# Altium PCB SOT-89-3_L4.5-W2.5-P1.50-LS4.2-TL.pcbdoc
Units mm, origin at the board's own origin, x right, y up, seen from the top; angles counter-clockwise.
Board outline 18.08 x 17.35 mm, 2 copper layers (Top Layer, Bottom Layer), stack 0.07 mm thick; 1 components, 0 nets, 3 pads, 0 vias.
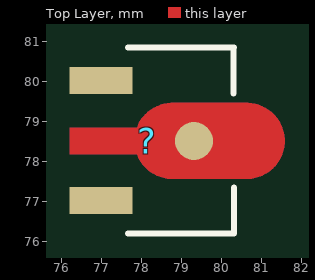
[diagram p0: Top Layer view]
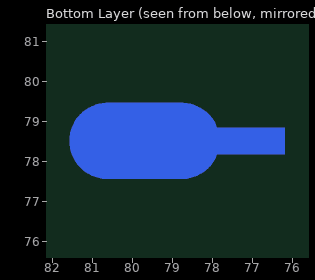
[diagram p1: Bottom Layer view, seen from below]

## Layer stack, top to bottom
Top Solder Mask Layer: solder mask 0.01, Dk 3.3
Top Layer: signal copper 0.035
Bottom Layer: signal copper 0.035
Bottom Solder Mask Layer: solder mask 0.01, Dk 3.3

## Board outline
87.927,69.85 69.85,69.85 69.85,87.202 87.927,87.202

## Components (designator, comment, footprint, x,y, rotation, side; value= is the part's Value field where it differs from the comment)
? "SOT-89-3_L4.5-W2.5-P1.50-LS4.2-TL" SOT-89-3_L4.5-W2.5-P1.50-LS4.2-TL 78.344,78.526 r0 top

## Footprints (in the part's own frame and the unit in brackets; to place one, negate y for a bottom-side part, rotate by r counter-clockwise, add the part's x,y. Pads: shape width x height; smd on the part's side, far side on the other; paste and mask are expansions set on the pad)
SOT-89-3_L4.5-W2.5-P1.50-LS4.2-TL [mm]
  rect 1.575x0.672 smd paste+0 mask+0.051: 1(-1.356,1.5) 3(-1.356,-1.5)
  round 0.95 smd: 2(0.966,-0.009)
  Top Layer region: 2.283,-0.959 0.429,-0.959 0.384,-0.958 0.34,-0.954 0.296,-0.949 0.252,-0.942 0.208,-0.933 0.165,-0.921 0.123,-0.908 0.081,-0.893 0.04,-0.875 0,-0.856 -0.04,-0.835 -0.078,-0.812 -0.115,-0.787 -0.151,-0.761 -0.185,-0.733 -0.219,-0.704 -0.251,-0.672 -0.281,-0.64 -0.31,-0.606 -0.337,-0.571 -0.362,-0.534 -0.386,-0.496 -0.408,-0.458 -0.428,-0.418 -0.447,-0.339 -2.144,-0.339 -2.144,0.321 -0.447,0.321 -0.428,0.401 -0.408,0.44 -0.386,0.479 -0.362,0.517 -0.337,0.553 -0.31,0.589 -0.281,0.623 -0.251,0.655 -0.219,0.686 -0.185,0.716 -0.151,0.744 -0.115,0.77 -0.078,0.795 -0.04,0.818 0,0.839 0.04,0.858 0.081,0.875 0.123,0.891 0.165,0.904 0.208,0.915 0.252,0.925 0.296,0.932 0.34,0.937 0.384,0.94 0.429,0.941 2.283,0.941 2.328,0.94 2.372,0.937 2.416,0.932 2.46,0.925 2.504,0.915 2.547,0.904 2.589,0.891 2.631,0.875 2.672,0.858 2.712,0.839 2.752,0.818 2.79,0.795 2.827,0.77 2.863,0.744 2.898,0.716 2.931,0.686 2.963,0.655 2.993,0.623 3.022,0.589 3.049,0.553 3.075,0.517 3.098,0.479 3.12,0.44 3.14,0.401 3.159,0.36 3.175,0.319 3.189,0.277 3.202,0.234 3.212,0.19 3.22,0.147 3.227,0.103 3.231,0.058 3.233,0.014 3.233,-0.031 3.231,-0.075 3.227,-0.12 3.22,-0.164 3.212,-0.208 3.202,-0.251 3.189,-0.294 3.175,-0.336 3.159,-0.377 3.14,-0.418 3.12,-0.458 3.098,-0.496 3.075,-0.534 3.049,-0.571 3.022,-0.606 2.993,-0.64 2.963,-0.672 2.931,-0.704 2.898,-0.733 2.863,-0.761 2.827,-0.787 2.79,-0.812 2.752,-0.835 2.712,-0.856 2.672,-0.875 2.631,-0.893 2.589,-0.908 2.547,-0.921 2.504,-0.933 2.46,-0.942 2.416,-0.949 2.372,-0.954 2.328,-0.958
  Bottom Layer region: 2.283,-0.959 0.429,-0.959 0.384,-0.958 0.34,-0.954 0.296,-0.949 0.252,-0.942 0.208,-0.933 0.165,-0.921 0.123,-0.908 0.081,-0.893 0.04,-0.875 0,-0.856 -0.04,-0.835 -0.078,-0.812 -0.115,-0.787 -0.151,-0.761 -0.185,-0.733 -0.219,-0.704 -0.251,-0.672 -0.281,-0.64 -0.31,-0.606 -0.337,-0.571 -0.362,-0.534 -0.386,-0.496 -0.408,-0.458 -0.428,-0.418 -0.447,-0.339 -2.144,-0.339 -2.144,0.321 -0.447,0.321 -0.428,0.401 -0.408,0.44 -0.386,0.479 -0.362,0.517 -0.337,0.553 -0.31,0.589 -0.281,0.623 -0.251,0.655 -0.219,0.686 -0.185,0.716 -0.151,0.744 -0.115,0.77 -0.078,0.795 -0.04,0.818 0,0.839 0.04,0.858 0.081,0.875 0.123,0.891 0.165,0.904 0.208,0.915 0.252,0.925 0.296,0.932 0.34,0.937 0.384,0.94 0.429,0.941 2.283,0.941 2.328,0.94 2.372,0.937 2.416,0.932 2.46,0.925 2.504,0.915 2.547,0.904 2.589,0.891 2.631,0.875 2.672,0.858 2.712,0.839 2.752,0.818 2.79,0.795 2.827,0.77 2.863,0.744 2.898,0.716 2.931,0.686 2.963,0.655 2.993,0.623 3.022,0.589 3.049,0.553 3.075,0.517 3.098,0.479 3.12,0.44 3.14,0.401 3.159,0.36 3.175,0.319 3.189,0.277 3.202,0.234 3.212,0.19 3.22,0.147 3.227,0.103 3.231,0.058 3.233,0.014 3.233,-0.031 3.231,-0.075 3.227,-0.12 3.22,-0.164 3.212,-0.208 3.202,-0.251 3.189,-0.294 3.175,-0.336 3.159,-0.377 3.14,-0.418 3.12,-0.458 3.098,-0.496 3.075,-0.534 3.049,-0.571 3.022,-0.606 2.993,-0.64 2.963,-0.672 2.931,-0.704 2.898,-0.733 2.863,-0.761 2.827,-0.787 2.79,-0.812 2.752,-0.835 2.712,-0.856 2.672,-0.875 2.631,-0.893 2.589,-0.908 2.547,-0.921 2.504,-0.933 2.46,-0.942 2.416,-0.949 2.372,-0.954 2.328,-0.958
  Multi-Layer region: 2.283,-0.959 0.429,-0.959 0.384,-0.958 0.34,-0.954 0.296,-0.949 0.252,-0.942 0.208,-0.933 0.165,-0.921 0.123,-0.908 0.081,-0.893 0.04,-0.875 0,-0.856 -0.04,-0.835 -0.078,-0.812 -0.115,-0.787 -0.151,-0.761 -0.185,-0.733 -0.219,-0.704 -0.251,-0.672 -0.281,-0.64 -0.31,-0.606 -0.337,-0.571 -0.362,-0.534 -0.386,-0.496 -0.408,-0.458 -0.428,-0.418 -0.447,-0.339 -2.144,-0.339 -2.144,0.321 -0.447,0.321 -0.428,0.401 -0.408,0.44 -0.386,0.479 -0.362,0.517 -0.337,0.553 -0.31,0.589 -0.281,0.623 -0.251,0.655 -0.219,0.686 -0.185,0.716 -0.151,0.744 -0.115,0.77 -0.078,0.795 -0.04,0.818 0,0.839 0.04,0.858 0.081,0.875 0.123,0.891 0.165,0.904 0.208,0.915 0.252,0.925 0.296,0.932 0.34,0.937 0.384,0.94 0.429,0.941 2.283,0.941 2.328,0.94 2.372,0.937 2.416,0.932 2.46,0.925 2.504,0.915 2.547,0.904 2.589,0.891 2.631,0.875 2.672,0.858 2.712,0.839 2.752,0.818 2.79,0.795 2.827,0.77 2.863,0.744 2.898,0.716 2.931,0.686 2.963,0.655 2.993,0.623 3.022,0.589 3.049,0.553 3.075,0.517 3.098,0.479 3.12,0.44 3.14,0.401 3.159,0.36 3.175,0.319 3.189,0.277 3.202,0.234 3.212,0.19 3.22,0.147 3.227,0.103 3.231,0.058 3.233,0.014 3.233,-0.031 3.231,-0.075 3.227,-0.12 3.22,-0.164 3.212,-0.208 3.202,-0.251 3.189,-0.294 3.175,-0.336 3.159,-0.377 3.14,-0.418 3.12,-0.458 3.098,-0.496 3.075,-0.534 3.049,-0.571 3.022,-0.606 2.993,-0.64 2.963,-0.672 2.931,-0.704 2.898,-0.733 2.863,-0.761 2.827,-0.787 2.79,-0.812 2.752,-0.835 2.712,-0.856 2.672,-0.875 2.631,-0.893 2.589,-0.908 2.547,-0.921 2.504,-0.933 2.46,-0.942 2.416,-0.949 2.372,-0.954 2.328,-0.958
  silkscreen extent -0.69,-2.33 1.96,2.33

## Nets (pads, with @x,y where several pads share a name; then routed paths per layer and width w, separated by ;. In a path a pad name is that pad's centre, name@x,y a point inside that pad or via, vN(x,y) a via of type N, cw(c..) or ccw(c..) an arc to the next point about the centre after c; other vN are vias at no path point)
pads on no net: ?.1 ?.2 ?.3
